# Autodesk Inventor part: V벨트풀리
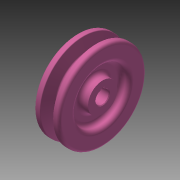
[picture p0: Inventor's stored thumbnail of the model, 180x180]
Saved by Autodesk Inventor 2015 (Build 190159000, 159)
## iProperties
Created: 2015-11
Part Number: V벨트풀리
Material: 강철, 탄소
Document SubType Name: Modeling
Designer: mduedu
Density: 1 g/cm^3
Appearance: 분홍색
Author: mduedu
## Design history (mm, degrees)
sketch "스케치1"
  geometry: L1 (-9.5, 0)-(9.5, 0); L2 (0, 0)-(0, 32.7); L3 (-4.825, 32.7)-(-9.5, 32.7); L4 (-9.5, 32.7)-(-9.5, 0); L5 (0, 23.7)-(-2.074, 23.7); L6 (-2.074, 23.7)-(-4.825, 32.7); L7 (4.825, 32.7)-(9.5, 32.7); L8 (9.5, 32.7)-(9.5, 0); L9 (0, 23.7)-(2.074, 23.7); L10 (2.074, 23.7)-(4.825, 32.7); L11 (-9.5, 30)-(9.5, 30); 3 further points
  constraints: 22 end point, 7 point on line, 4 perpendicular, 3 symmetric about line, 1 coincident, 1 horizontal, 1 horizontal alignment, 1 midpoint, 1 vertical
  dimensions: "d0" = 19 distance of L1.start L1.end; "d2" = 65.4 diameter of L2.end L1 (derived); "d3" = 34 deg angle of L10 L6; "d4" = 6.3 distance between parallel lines of L11 L9; "d5" = 2.7 distance between parallel lines of L7 L11; "d6" = 8 distance of point (4, 30) point (-4, 30); "d7" = 60 diameter of L11 L1
revolve "회전1" sketch "스케치1" stored, may be unused: angle "d8" = 90 deg
sketch "스케치2"
  geometry: C1 r 20 at (0, 0); C2 r 11 at (0, 0); 1 further point
  constraints: 2 centre point, 2 coincident
  dimensions: "d9" = 40 diameter of C1; "d10" = 22 diameter of C2
extrude "돌출1" cut sketch "스케치2" distance "d11" = 6; taper "d12" = 0 deg
fillet "모깎기1" dims "d13" = 3
fillet "모깎기2" dims "d14" = 3
fillet "모깎기3" dims "d15" = 1, "d16" = 0.5, "d17" = 2
hole "구멍1" diameter "d20" = 10; stored, may be unused: countersink angle "d24" = 90 deg, drill point angle "d26" = 118 deg; dims "d18" = 10, "d19" = 10, "d21" = 6, "d22" = 4, "d23" = 2, "d25" = 8
sketch "스케치3"
  geometry: L1 (-1.5, 0)-(1.5, 0); L2 (1.5, 0)-(1.5, 6.4); L3 (1.5, 6.4)-(-1.5, 6.4); L4 (-1.5, 6.4)-(-1.5, 0); 2 further points
  constraints: 8 end point, 2 parallel, 1 coincident, 1 horizontal, 1 midpoint, 1 perpendicular
  dimensions: "d27" = 3 distance of L2.end L3.end; "d29" = 6.4 distance of L3.end L1.start
extrude "돌출2" cut sketch "스케치3" stored distance "d30" = 6; taper "d31" = 0 deg
chamfer "모따기1" distance "d32" = 0.5; stored, may be unused: second distance "d33" = 2, angle "d34" = 45 deg
node "솔리드1"
mirror "대칭1"
